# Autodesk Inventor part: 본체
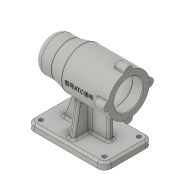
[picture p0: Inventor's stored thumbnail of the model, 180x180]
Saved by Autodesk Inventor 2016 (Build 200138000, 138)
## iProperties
Created: 2019-07
Part Number: 본체
Material: 일반
Document SubType Name: Modeling
Designer: 3sil_cad003
Density: 1 g/cm^3
Appearance: 기본값
Author: 3sil_cad003
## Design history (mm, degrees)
sketch "스케치1"
  geometry: L1 (-56, 35)-(56, 35); L2 (56, 35)-(56, -35); L3 (56, -35)-(-56, -35); L4 (-56, -35)-(-56, 35); L5 (-56, 35)-(56, -35); L6 (56, 35)-(-56, -35); 1 further point
  constraints: 12 end point, 2 midpoint, 2 parallel, 1 horizontal, 1 perpendicular
  dimensions: "d0" = 112 distance of L2.end L3.end; "d1" = 70 distance of L3.end L1.start
extrude "돌출1" new body sketch "스케치1" distance "d2" = 10; taper "d3" = 0 deg
sketch "스케치2"
  geometry: L1 (-56, 0)-(56, 0) reference; L2 (-56, 80)-(56, 80); L3 (-56, 80)-(-56, 105); L4 (-56, 105)-(-31, 105); L5 (-31, 105)-(-11, 110); L6 (-11, 110)-(56, 110); L7 (56, 110)-(56, 80); L8 (-50, 80)-(-50, 90.5); L9 (-50, 90.5)-(-47, 90.5); L10 (-47, 90.5)-(-47, 96); L11 (-47, 96)-(-43, 96); L12 (-43, 96)-(-43, 97.5); L13 (-43, 97.5)-(-25, 97.5); L14 (-25, 97.5)-(-25, 101); L15 (-25, 101)-(-13, 101); L16 (-13, 101)-(-13, 104); L17 (-13, 104)-(41, 104); L18 (41, 104)-(41, 101); L19 (41, 101)-(56, 101); 1 further point
  constraints: 36 end point, 14 perpendicular, 2 point on line, 1 horizontal, 1 parallel, 1 vertical
  dimensions: "d6" = 112 distance of L2.start L2.end; "d7" = 80 distance from line of L2 point (0, 0); "d8" = 56 horizontal distance of point (0, 0) L2.start (= 0.5 x d6); "d9" = 50 diameter of L4 L2; "d10" = 60 diameter of L6 L2; "d11" = 25 distance of L3.end L4.end; "d12" = 45 distance from line of L5.end L3; "d13" = 21 diameter of L9 L2; "d14" = 3 distance of L8.end L9.end; "d15" = 32 diameter of L11 L2; "d16" = 4 distance of L10.end L11.end; "d17" = 18 distance of L12.end L13.end; "d18" = 12 distance of L14.end L15.end; "d19" = 35 diameter of L13 L2; "d20" = 42 diameter of L15 L2; "d21" = 48 diameter of L17 L2; "d22" = 54 distance between parallel lines of L18 L16; "d23" = 15 distance of L18.end L19.end; "d24" = 42 diameter of L19 L2
revolve "회전1" sketch "스케치2" stored, may be unused: angle "d25" = 90 deg
sketch "스케치3"
  geometry: C1 r 30 at (0, 0) reference; C2 r 30 at (0, 0) reference; C3 r 30 at (0, 0) reference; C4 r 21 at (0, 0) reference; C5 r 6 at (0, 30); 1 further point
  constraints: 1 centre point
  dimensions: "d27" = 30 distance of C1.centre C5.centre; "d28" = 12 diameter of C5
extrude "돌출2" join sketch "스케치3" distance "d29" = 16; taper "d30" = 0 deg
sketch "스케치4"
  geometry: A1 r 6 centre (0, 0) between (5.97, -0.6) and (-5.97, -0.6) reference; 2 further points
  constraints: 1 coincident
hole "구멍1" sketch "스케치4" at (0, 0) diameter "d31" = 3.242; stored, may be unused: countersink angle "d35" = 90 deg, drill point angle "d37" = 118 deg; dims "d32" = 8, "d33" = 4, "d34" = 2, "d36" = 11
sketch "스케치5"
  geometry: L1 (56, 10)-(-56, 10) reference; L2 (-36, 10)-(-28.334, 31.063); 1 further point
  constraints: 2 end point, 1 point on line
  dimensions: "d41" = 110 deg angle of L1 L2; "d42" = 20 distance of L2.start L1.end
feature "리브1" sketch "스케치5" dims "d43" = 40, "d44" = 8, "d45" = 0, "d46" = 0, "d47" = 1, "d48" = 1
sketch "스케치6"
  geometry: L1 (56, -35)-(56, 35) reference; L2 (0, 4)-(31, 4); L3 (31, 4)-(31, -4); L4 (31, -4)-(0, -4); L5 (0, -4)-(0, 4); 1 further point
  constraints: 8 end point, 2 parallel, 1 horizontal, 1 perpendicular
  dimensions: "d50" = 25 distance between parallel lines of L1 L3; "d51" = 0 distance from line of point (0, 0) L5; "d52" = 8 distance of L2.end L3.end; "d53" = 4 distance of L4.end point (0, 0)
extrude "돌출3" join sketch "스케치6" stored distance "d54" = 16; taper "d55" = 0 deg
sketch "스케치7"
  geometry: L1 (10, -35)-(10, 35) reference; L2 (10, 28)-(34.996, 23.592); 1 further point
  constraints: 2 end point, 1 point on line
  dimensions: "d56" = 100 deg angle of L1 L2; "d57" = 7 distance of L2.start L1.end
feature "리브2" sketch "스케치7" dims "d58" = 40, "d59" = 8, "d60" = 0, "d61" = 0, "d62" = 1, "d63" = 1
fillet "모깎기1" dims "d64" = 10
sketch "스케치10"
  geometry: A1 r 10 centre (-46, 25) between (-46, 35) and (-56, 25) reference; A2 r 10 centre (-46, -25) between (-56, -25) and (-46, -35) reference; A3 r 10 centre (46, -25) between (46, -35) and (56, -25) reference; A4 r 10 centre (46, 25) between (56, 25) and (46, 35) reference; 1 further point
hole "구멍2" sketch "스케치10" at (-46, 25), (-46, -25), (46, 25), (46, -25) diameter "d65" = 6; stored, may be unused: countersink angle "d69" = 90 deg, drill point angle "d71" = 118 deg; dims "d66" = 8, "d67" = 4, "d68" = 2, "d70" = 11
fillet "모깎기3" dims "d73" = 10
fillet "모깎기4" dims "d74" = 3
fillet "모깎기6" dims "d76" = 3
fillet "모깎기7" dims "d77" = 1
fillet "모깎기8" dims "d78" = 3
fillet "모깎기9" dims "d79" = 3
fillet "모깎기10" dims "d80" = 3
fillet "모깎기11" dims "d81" = 0.3
chamfer "모따기1" distance "d82" = 1; stored, may be unused: second distance "d83" = 1, angle "d84" = 45 deg
chamfer "모따기2" distance "d85" = 3; stored, may be unused: second distance "d86" = 1, angle "d87" = 45 deg
fillet "모깎기12" dims "d88" = 3
fillet "모깎기13" dims "d89" = 3
fillet "모깎기14" dims "d90" = 3
node "작업 평면1"
sketch "스케치11"
  geometry: L1 (56, 86.771)-(56, 109.226) reference; L2 (46, 0)-(-46, 0) reference; 2 further points
  constraints: 1 other
  dimensions: "d92" = 42 distance from line of L1 point (14, 80); "d93" = 80 distance from line of L2 point (14, 80)
feature "엠보싱1" sketch "스케치11" dims "d0" = 112, "d1" = 70, "d94" = 0.5, "d95" = 0
node "솔리드1"
pattern_circular "원형 패턴1" dims angle "d39" = 360 deg
mirror "대칭1"
node "투영된 루프1"
